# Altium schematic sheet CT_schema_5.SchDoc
size 293 x 258 mm
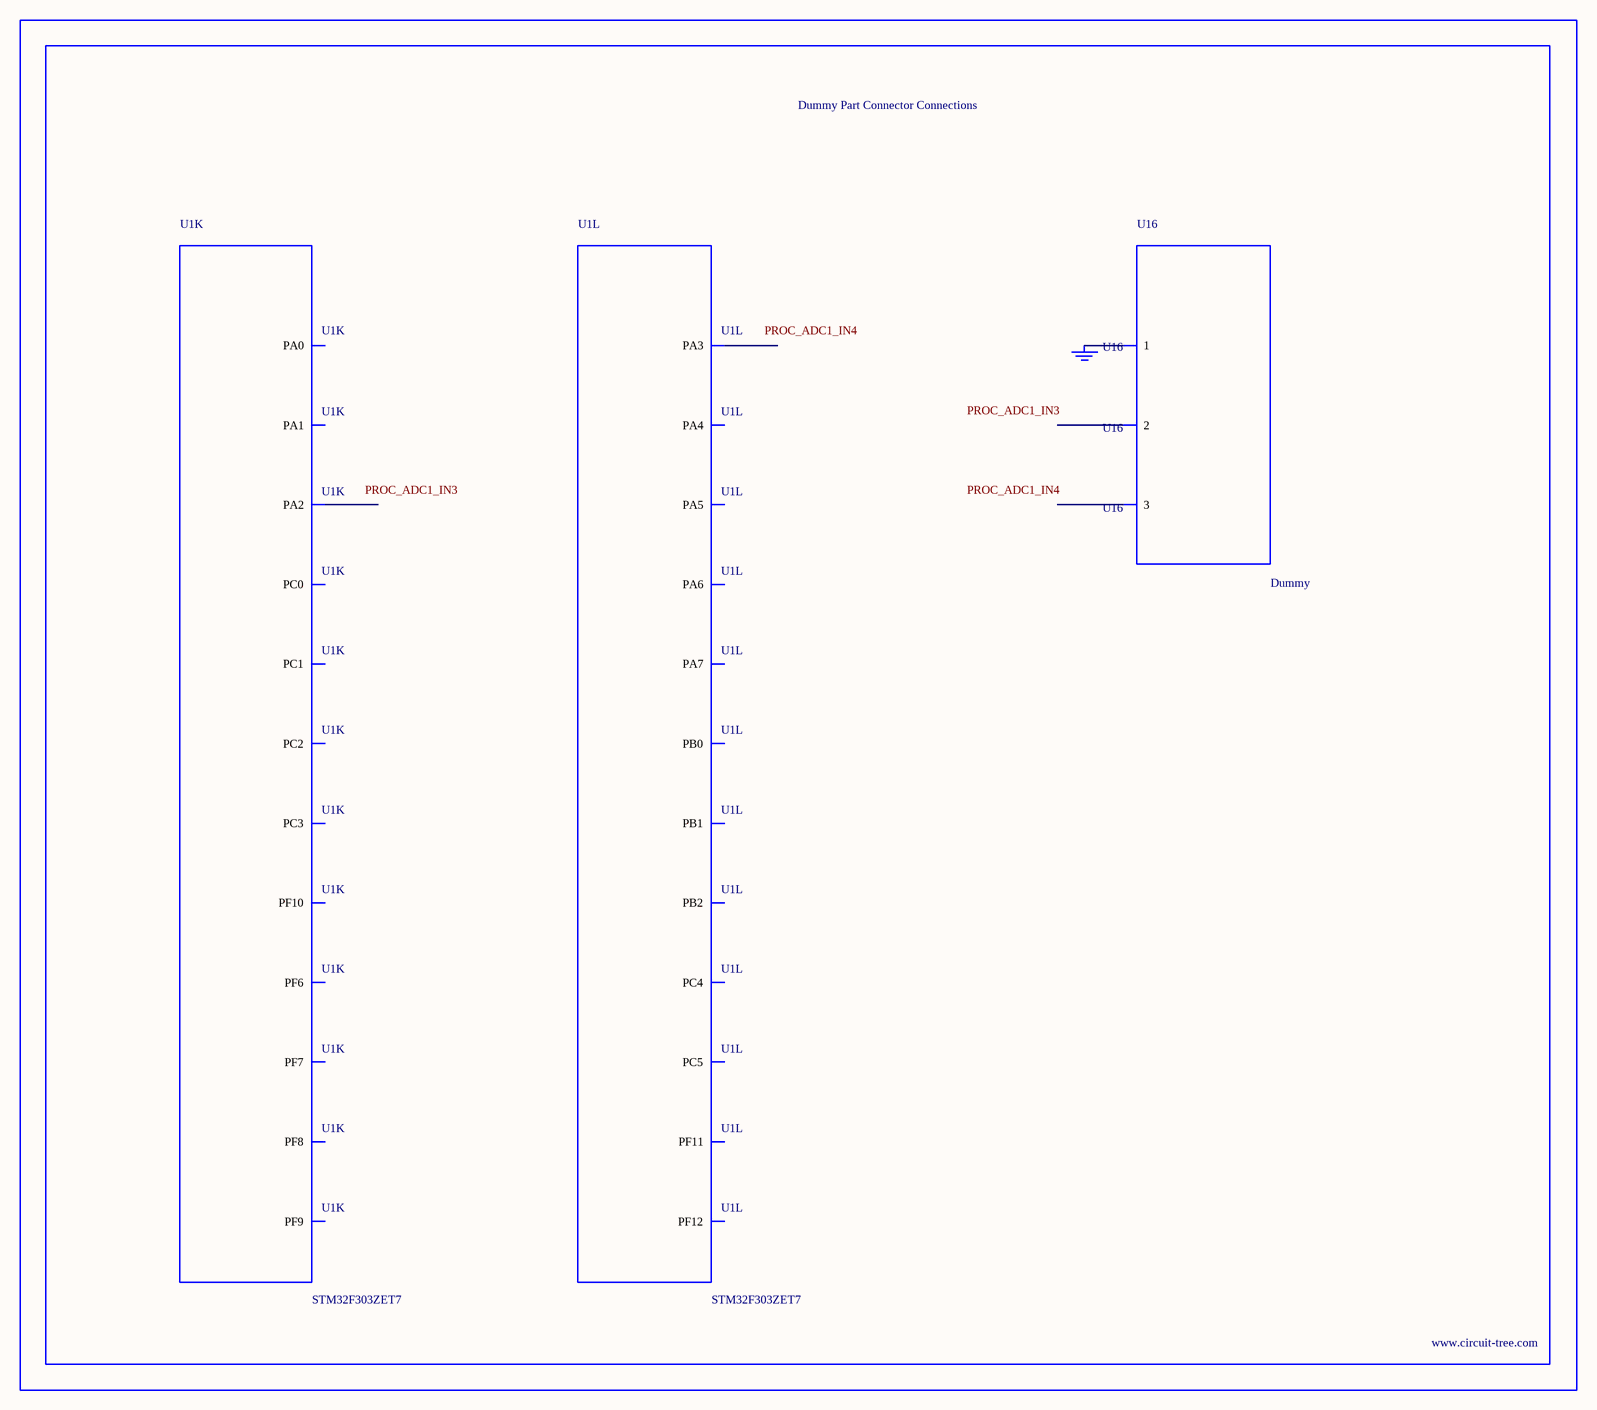
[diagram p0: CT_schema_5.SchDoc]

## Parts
BORDER4  (no value)
GND_INSTANCE_4_0  (no value)
U1  STM32F303ZET7  [LQFP144]  (parts K,L of 12)
U16  Dummy  [DUMMY_PACKAGE_150]

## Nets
NetGND_INSTANCE_4_0_0: GND_INSTANCE_4_0.0(GND) U16.1

Not connected (* = marked no-connect by the designer): U1 18(PF6) 19(PF7) 20(PF8) 21(PF9) 22(PF10) 26(PC0) 27(PC1) 28(PC2) 29(PC3) 34(PA0) 35(PA1) 36(PA2) 37(PA3) 40(PA4) 41(PA5) 42(PA6) 43(PA7) 44(PC4) 45(PC5) 46(PB0) 47(PB1) 48(PB2) 49(PF11) 50(PF12); U16 2 3

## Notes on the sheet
- Labels drawn without touching a wire or pin: PROC_ADC1_IN3, PROC_ADC1_IN4

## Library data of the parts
BORDER4 = BORDER_PAGE4
GND_INSTANCE_4_0 = GND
